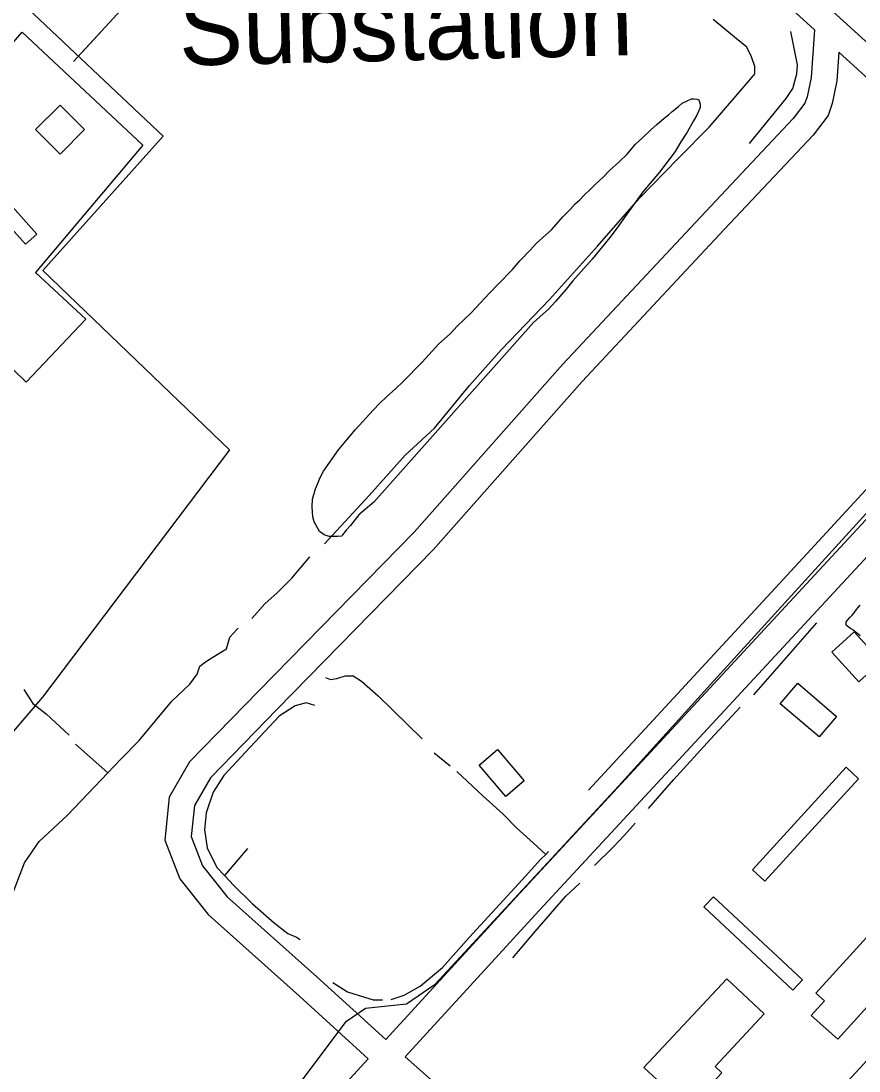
# Model space of a CAD drawing. Extents: x 3355677 to 3393573, y 612928 to 638357.
# Drawn here: x 3383445 to 3384413, y 620542 to 621756 of the extents above; entities that cross this region are included whole.
import ezdxf

# ---------------------------------------------------------------- set-up
doc = ezdxf.new("R2010")
doc.units = 0
for name, color, linetype in [('V-BLDG-OTLN', 7, 'Continuous'), ('V-ROAD-CNTR', 7, 'Continuous'), ('V-SITE-OTLN', 7, 'Continuous'), ('V-SITE-OTLN-IDEN', 7, 'Continuous'), ('V-SITE-VEGE', 7, 'Continuous'), ('V-TOPO-SHOR', 7, 'Continuous'), ('V-UTIL-LINE', 7, 'Continuous')]:
    doc.layers.add(name, color=color, linetype=linetype)

msp = doc.modelspace()

# ---------------------------------------------------------------- linework, layer by layer
at = {"layer": 'V-BLDG-OTLN'}
for points in [[(3383462, 621630.1), (3383490.3, 621601.8), (3383518.6, 621630.1), (3383490.3, 621658.4)], [(3383450.3, 621497.6), (3383409.8, 621542.9), (3383423, 621554.7), (3383463.5, 621509.4)], [(3384407.4, 621049.9), (3384438.6, 621015.7), (3384412.9, 620992.2), (3384381.7, 621026.4)], [(3384342.5, 620990.4), (3384387.2, 620952.1), (3384366.9, 620928.4), (3384322.2, 620966.6)], [(3383995.4, 620913.7), (3384026.2, 620877.5), (3384005.2, 620859.7), (3383974.5, 620895.9)], [(3384290.2, 620775), (3384398.2, 620893.3), (3384412.6, 620880.1), (3384304.4, 620761.6)], [(3384363.3, 620632.2), (3384476.6, 620757.1), (3384516.9, 620720.5), (3384388.5, 620579), (3384358, 620606.6), (3384373.1, 620623.3)], [(3384245.1, 620743.7), (3384347.7, 620647.6), (3384336.7, 620635.9), (3384233.9, 620732.2)], [(3384164.5, 620546.3), (3384260.6, 620648.9), (3384303.7, 620608.5), (3384246.9, 620547.7), (3384254.7, 620540.3), (3384214.7, 620497.6), (3384221.3, 620491.3), (3384182, 620449.3), (3384152.9, 620476.6), (3384165.5, 620490.1), (3384157.1, 620498), (3384164.7, 620506.1), (3384159.4, 620511.1), (3384179.5, 620532.6)]]:
    msp.add_lwpolyline(points, close=True, dxfattribs=at)
at = {"layer": 'V-ROAD-CNTR'}
for points in [[(3385481.3, 623640.8), (3385415.1, 623572.1), (3385005.6, 623128.5), (3384655.4, 622744.6), (3384187.8, 622244.8), (3384105.9, 622152.4), (3384086.4, 622117.1), (3384079.3, 622091.2), (3384083.5, 622062.8), (3384106.1, 622018.8), (3384188.5, 621943.8), (3384500.7, 621659.3), (3384654, 621512.8), (3384841.1, 621336.5), (3385030.9, 621162.8)], [(3384052, 622070.9), (3384054.5, 622053.5), (3384081.8, 622000.3), (3384168.3, 621921.6), (3384361.7, 621745.4)], [(3384361.7, 621745.4), (3384357.7, 621690.4), (3384353.2, 621668.1), (3384350.7, 621660.6), (3384337.1, 621643), (3384235.7, 621535.1), (3384071, 621359.1), (3383899.5, 621164.8), (3383719.8, 620981.5), (3383640, 620899.5), (3383616.4, 620858.8), (3383611.3, 620809.2), (3383628.5, 620764.5), (3383661.5, 620723.1)], [(3384389.9, 621719.7), (3384387.5, 621686.3), (3384382.2, 621660.3), (3384377.5, 621646.4), (3384360, 621623.5), (3384257.5, 621514.6), (3384093.2, 621338.9), (3383921.4, 621144.4), (3383741.2, 620960.5), (3383664.1, 620881.2), (3383645.5, 620849.3), (3383641.9, 620813.3), (3383654.8, 620779.6), (3383683.4, 620743.8)], [(3384389.9, 621719.7), (3384480.3, 621637.3), (3384633.3, 621491), (3384674.3, 621452.4)], [(3383866.5, 620578.7), (3384017, 620743.1), (3384420.6, 621178.7), (3384627.7, 621402.9), (3384674.3, 621452.4)], [(3383888.8, 620558.7), (3384039, 620722.7), (3384442.7, 621158.3), (3384649.6, 621382.5), (3384696.1, 621431.8)], [(3383683.4, 620743.8), (3383787, 620651.3), (3383866.5, 620578.7)], [(3383661.5, 620723.1), (3383766.9, 620629), (3383846.2, 620556.6)], [(3382611.9, 619214.6), (3382746.5, 619360.1), (3383141.8, 619791.9), (3383588.7, 620275.3), (3383846.2, 620556.6)], [(3383888.8, 620558.7), (3384030, 620433.8), (3384205, 620271.5)]]:
    msp.add_lwpolyline(points, dxfattribs=at)
at = {"layer": 'V-SITE-OTLN'}
for p, q in [((3383306.5, 621908.8), (3383609.6, 621622.6)), ((3383609.6, 621622.6), (3383470.3, 621467.3)), ((3383470.3, 621467.3), (3383686.2, 621260.2)), ((3384241.5, 620989.1), (3384666.6, 621456.6)), ((3383686.2, 621260.2), (3383469.9, 620974.3)), ((3384135.4, 620871.5), (3384241.5, 620989.1)), ((3383469.9, 620974.3), (3383353.7, 620838.2)), ((3383923.7, 620642.9), (3384135.4, 620871.5)), ((3383890.4, 620620), (3383923.7, 620642.9)), ((3383821.3, 620599.9), (3383843.3, 620614.9)), ((3383843.3, 620614.9), (3383890.4, 620620)), ((3383631.8, 620349.3), (3383821.3, 620599.9))]:
    msp.add_line(p, q, dxfattribs=at)
msp.add_lwpolyline([(3383586.1, 621612.2), (3383462, 621465.1), (3383520.1, 621411), (3383451.3, 621338.1), (3383393.2, 621394.6), (3383377.2, 621376.1), (3383353.7, 621395.7), (3383303.3, 621345), (3383136.4, 621497.4), (3383290, 621668), (3383339.5, 621620.1), (3383446.4, 621742.5)], close=True, dxfattribs=at)
at = {"layer": 'V-SITE-VEGE'}
msp.add_lwpolyline([(3383852.8, 621199.5), (3383835.6, 621184.9), (3383825.6, 621172.7), (3383820.6, 621167.1), (3383816.7, 621162), (3383815.6, 621160.4), (3383811.1, 621159.8), (3383801.1, 621159.8), (3383795.5, 621162), (3383789.9, 621165.9), (3383787.7, 621169.8), (3383783.8, 621177), (3383782.1, 621182.5), (3383781.5, 621194.2), (3383782, 621203.2), (3383785.3, 621214.9), (3383787.5, 621220.4), (3383790.9, 621228.2), (3383794.7, 621235.5), (3383811.9, 621260.1), (3383821.4, 621271.8), (3383831.4, 621283.5), (3383851.9, 621305.9), (3383859.7, 621314.2), (3383866.9, 621320.9), (3383878, 621331), (3383886.3, 621338.8), (3383908.5, 621361.2), (3383928, 621382.4), (3383940.8, 621394.1), (3383949.1, 621403.1), (3383965.2, 621418.2), (3383970.7, 621424.3), (3383986.3, 621441.1), (3383996.3, 621451.7), (3384012.9, 621468.4), (3384021.3, 621478.5), (3384033.5, 621491.3), (3384040.1, 621498.6), (3384051.2, 621508.7), (3384057.9, 621514.2), (3384065.7, 621523.2), (3384071.2, 621529.3), (3384079.6, 621537.7), (3384085.1, 621544.4), (3384090.7, 621548.9), (3384095.1, 621553.9), (3384103.4, 621561.7), (3384107.9, 621566.2), (3384117.9, 621575.7), (3384125.1, 621583), (3384136.2, 621593), (3384145.1, 621601.4), (3384155.1, 621613.1), (3384162.9, 621620.4), (3384172.9, 621630.4), (3384179.5, 621636), (3384187.9, 621643.3), (3384192.9, 621647.2), (3384197.3, 621651.1), (3384204.5, 621656.7), (3384209, 621660.6), (3384214.5, 621663.4), (3384219.5, 621665.7), (3384222.3, 621665.7), (3384225.7, 621665.1), (3384227.9, 621664.6), (3384229.6, 621659.6), (3384229.6, 621655.7), (3384225.7, 621646.8), (3384221.9, 621640.1), (3384214.6, 621627.2), (3384207.4, 621616.1), (3384200.8, 621604.9), (3384182.5, 621580.9), (3384163.6, 621558), (3384144.8, 621532.3), (3384133.7, 621516.7), (3384125.3, 621505.5), (3384104.8, 621480.4), (3384082.6, 621455.3), (3384074.8, 621445.8), (3384062.6, 621431.3), (3384054.9, 621422.9), (3384037.1, 621407.2)], close=True, dxfattribs=at)
at = {"layer": 'V-TOPO-SHOR'}
for p, q in [((3384291.7, 620977.1), (3384364.2, 621060.4)), ((3383508.3, 620920.1), (3383545.6, 620886.8)), ((3383922.4, 620910.1), (3383940.9, 620894.8)), ((3383706.9, 620799.3), (3383680.3, 620768.2))]:
    msp.add_line(p, q, dxfattribs=at)
for points in [[(3383795.7, 621151.5), (3383847.5, 621207.4), (3383889, 621253.8), (3383922.9, 621285.1), (3383963.4, 621334.4), (3384000.1, 621376), (3384055.6, 621433.8), (3384111.2, 621495.4), (3384159.2, 621550.4), (3384204.4, 621596.8), (3384240.2, 621632.8), (3384287.3, 621687.8), (3384292.9, 621694.4), (3384292.9, 621702.9), (3384289.1, 621714.2), (3384283.4, 621725.5), (3384269.2, 621736.8), (3384244.6, 621757.5)], [(3384286.6, 621613.9), (3384329, 621666), (3384336.5, 621677.4), (3384341.2, 621694.4), (3384342.1, 621704.8), (3384334.4, 621743.5)], [(3384100.7, 620867), (3384189.2, 620962.7), (3384316.4, 621100.1), (3384480.2, 621278.2), (3384541.4, 621342.6), (3384554.6, 621358.7), (3384562.1, 621372.9), (3384572.5, 621397.5), (3384588.3, 621456.1), (3384603.3, 621515.7)], [(3383711.9, 621065.3), (3383727, 621082.3), (3383741.1, 621094.7), (3383758.1, 621111.7), (3383778.8, 621136.3)], [(3384414.6, 621045.3), (3384411.6, 621047.6), (3384408.5, 621050), (3384406, 621052), (3384403.3, 621053.8), (3384400.6, 621055.7), (3384398.3, 621057.7), (3384398.4, 621061.2), (3384400.3, 621063.7), (3384402.8, 621066.6), (3384405.2, 621069), (3384407.4, 621071.7), (3384410, 621075.5), (3384412.1, 621077.9), (3384414.5, 621080.6)], [(3383299.7, 620528.3), (3383359, 620592.8), (3383385.4, 620622.1), (3383396.7, 620645.8), (3383408.8, 620685.5), (3383432.3, 620738.5), (3383449.2, 620782.9), (3383466.1, 620807.6), (3383499.1, 620837.9), (3383545.6, 620886.8), (3383560.3, 620902.3), (3383581.9, 620924.1), (3383619.6, 620969.6), (3383640.3, 620989.5), (3383648.8, 621000.8), (3383651.6, 621010.3), (3383658.2, 621015), (3383666.7, 621020.7), (3383682.7, 621030.2), (3383686.5, 621043.5), (3383694.9, 621052.9), (3383695.9, 621053.9)], [(3383796.8, 620996.9), (3383802.8, 620994.6), (3383809.9, 620995.8), (3383814.7, 620997.6), (3383820, 620998.8), (3383828.9, 620998.9), (3383838.5, 620993), (3383857.7, 620975.8), (3383908.6, 620926.1)], [(3383448.6, 620983.2), (3383459, 620967.2), (3383474.2, 620955), (3383500.7, 620930.5)], [(3383784.5, 620964.7), (3383774.4, 620967.6), (3383761.9, 620964.5), (3383743.5, 620952.5), (3383709.8, 620916.6), (3383679.6, 620883.7), (3383667.2, 620864.5), (3383659, 620840.7), (3383657.3, 620821), (3383660.4, 620800.2), (3383671.3, 620777.6), (3383680.3, 620768.2), (3383691.1, 620756.9), (3383712.6, 620735.6), (3383737.8, 620713.7), (3383753.3, 620701.3), (3383763.5, 620697.2), (3383767.7, 620694.3)], [(3384169.9, 620845.5), (3384198.8, 620879), (3384241.4, 620925.7), (3384275.7, 620962.9)], [(3383948.7, 620888.3), (3383978.6, 620860.5), (3384002, 620839.2), (3384017.6, 620823.2), (3384036.7, 620806), (3384051.4, 620792.7)], [(3384107.7, 620779.7), (3384129, 620801.2), (3384142.1, 620815), (3384154.5, 620828.8)], [(3383872.9, 620625.2), (3383887.7, 620630.1), (3383906.1, 620640.3), (3383932.2, 620661.9), (3383962.9, 620696.6), (3384023.9, 620763.1), (3384045.8, 620787), (3384051.4, 620792.7), (3384054.6, 620796)], [(3384013.1, 620673.1), (3384039.1, 620703.6), (3384074.6, 620744.3), (3384090.6, 620759.3)], [(3383805.5, 620644.5), (3383822.2, 620633.8), (3383840.7, 620628), (3383852, 620624.5), (3383862.8, 620624.6)]]:
    msp.add_lwpolyline(points, dxfattribs=at)
at = {"layer": 'V-UTIL-LINE'}
for points in [[(3387735.2, 628787.2), (3384417.1, 624919.5), (3385450.1, 623817.3), (3383505.8, 621708.7)], [(3383538.9, 621744.6), (3383515.8, 621719.6)], [(3384184.3, 620296), (3384552.9, 620696.6)]]:
    msp.add_lwpolyline(points, dxfattribs=at)

# ---------------------------------------------------------------- texts
at = {"layer": 'V-SITE-OTLN-IDEN'}
msp.add_text('Substation', height=83, rotation=1.3328, dxfattribs=at).set_placement((3383628.3, 621704))

doc.saveas('drawing.dxf')
